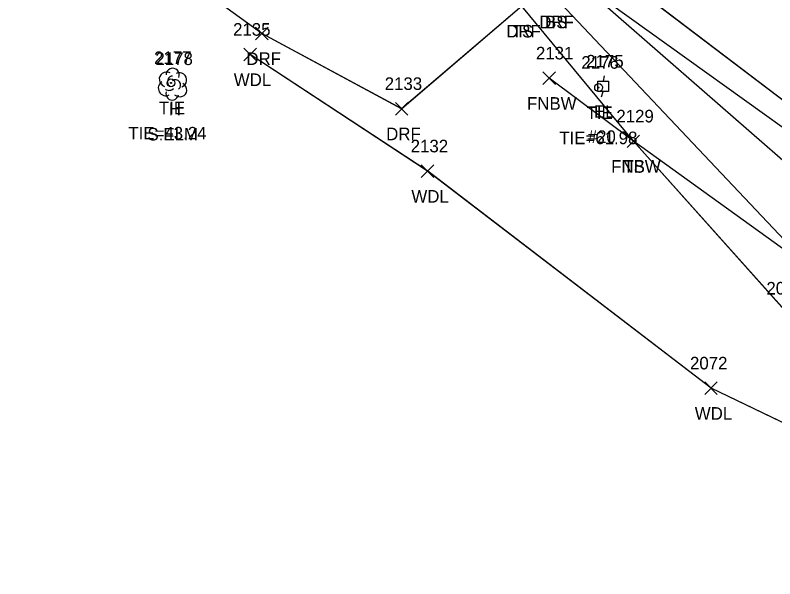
# Model space of a CAD drawing. Extents: x 1415642 to 1422021, y 544543 to 547232.
# Drawn here: x 1415652.6 to 1415773.3, y 547024.6 to 547114.3 of the extents above; entities that cross this region are included whole.
import ezdxf

# ---------------------------------------------------------------- set-up
doc = ezdxf.new("R2010")
doc.units = 0
for name, color, linetype in [('C_A', 7, 'Continuous'), ('C_C', 7, 'Continuous'), ('C_I', 7, 'Continuous'), ('CBP', 7, 'Continuous'), ('L_A', 7, 'Continuous'), ('L_C', 7, 'Continuous'), ('L_I', 7, 'Continuous'), ('L_TIC', 7, 'Continuous'), ('LAWA', 7, 'Continuous'), ('LELB', 7, 'Continuous'), ('LFNC', 7, 'Continuous'), ('LTD', 7, 'Continuous'), ('PET', 7, 'Continuous'), ('R_A', 7, 'Continuous'), ('R_I', 7, 'Continuous'), ('R_TIC', 7, 'Continuous'), ('RDF', 7, 'Continuous'), ('U_A', 7, 'Continuous'), ('U_C', 7, 'Continuous'), ('U_I', 7, 'Continuous'), ('UEPT', 7, 'Continuous')]:
    doc.layers.add(name, color=color, linetype=linetype)

msp = doc.modelspace()

# ---------------------------------------------------------------- linework, layer by layer
at = {"layer": 'CBP'}
for centre, radius in [((1415677.36, 547103.51), 0.625), ((1415677.36, 547103.51), 0.0833), ((1415745.31, 547102.76), 0.625), ((1415745.31, 547102.76), 0.0833)]:
    msp.add_circle(centre, radius, dxfattribs=at)
at = {"layer": 'L_TIC'}
for points in [[(1415688.93, 547107.01), (1415690.93, 547109.01)], [(1415690.93, 547107.01), (1415688.93, 547109.01)], [(1415736.47, 547103.24), (1415738.47, 547105.24)], [(1415738.47, 547103.24), (1415736.47, 547105.24)], [(1415749.83, 547093.22), (1415751.83, 547095.22)], [(1415751.83, 547093.22), (1415749.83, 547095.22)], [(1415749.83, 547093.22), (1415751.83, 547095.22)], [(1415751.83, 547093.22), (1415749.83, 547095.22)], [(1415717.14, 547088.46), (1415719.14, 547090.46)], [(1415719.14, 547088.46), (1415717.14, 547090.46)], [(1415762.17, 547053.94), (1415764.17, 547055.94)], [(1415764.17, 547053.94), (1415762.17, 547055.94)]]:
    msp.add_lwpolyline(points, dxfattribs=at)
at = {"layer": 'LAWA'}
for points in [[(1415914.11, 546834.35), (1415931.31, 546850.74), (1415944.85, 546869.92), (1415908.68, 546903.98), (1415882.09, 546945.44), (1415862.73, 546979.72), (1415851.29, 546999.16), (1415831.18, 547012.42), (1415802.21, 547036.19), (1415763.17, 547054.94), (1415718.14, 547089.46), (1415689.93, 547108.01)], [(1415914.12, 546834.35), (1415931.31, 546850.75), (1415944.86, 546869.92), (1415908.68, 546903.98), (1415882.1, 546945.44), (1415862.73, 546979.72), (1415851.29, 546999.15), (1415831.18, 547012.42), (1415802.2, 547036.19), (1415763.17, 547054.94), (1415718.15, 547089.45), (1415689.93, 547108.01)]]:
    msp.add_lwpolyline(points, dxfattribs=at)
at = {"layer": 'LELB'}
for points in [[(1415821.69, 547055.02), (1415783.27, 547083.61), (1415741.01, 547120.53), (1415723.94, 547132.39), (1415695.54, 547155.33), (1415675.42, 547170.57)], [(1415821.7, 547055.02), (1415783.28, 547083.61), (1415741.01, 547120.53), (1415723.94, 547132.38), (1415695.54, 547155.33), (1415675.42, 547170.56)], [(1415851.29, 546999.16), (1415835.48, 547016.01), (1415808.9, 547044.81), (1415779.47, 547073.63), (1415738.35, 547117.19), (1415722.7, 547128.21), (1415693.4, 547151.97), (1415674.17, 547168.64)], [(1415851.29, 546999.15), (1415835.48, 547016.02), (1415808.9, 547044.81), (1415779.47, 547073.63), (1415738.34, 547117.19), (1415722.7, 547128.21), (1415693.4, 547151.96), (1415674.17, 547168.64)], [(1415802.21, 547036.19), (1415775.31, 547066.85), (1415750.83, 547094.22), (1415733.1, 547115.73), (1415720.57, 547124.98), (1415690.99, 547148.71), (1415672.49, 547166.01)], [(1415802.2, 547036.19), (1415775.31, 547066.86), (1415750.83, 547094.23), (1415733.1, 547115.73), (1415720.57, 547124.98), (1415690.99, 547148.71), (1415672.49, 547166.01)], [(1415979.27, 546932.57), (1415964.6, 546940.59), (1415957.63, 546956.7), (1415934.73, 546972.98), (1415912.21, 546991.17), (1415886.95, 547011.09), (1415854.08, 547036.67), (1415824.18, 547059.44), (1415786.82, 547087.62), (1415741.01, 547120.53)], [(1415979.28, 546932.57), (1415964.61, 546940.59), (1415957.63, 546956.7), (1415934.74, 546972.98), (1415912.22, 546991.17), (1415886.96, 547011.09), (1415854.08, 547036.67), (1415824.19, 547059.44), (1415786.82, 547087.62), (1415741.01, 547120.53)]]:
    msp.add_lwpolyline(points, dxfattribs=at)
at = {"layer": 'LFNC'}
for points in [[(1415844.05, 547025.19), (1415815.91, 547049.29), (1415779.47, 547073.63), (1415750.83, 547094.22), (1415737.47, 547104.24)], [(1415844.05, 547025.19), (1415815.91, 547049.29), (1415779.47, 547073.63), (1415750.83, 547094.23), (1415737.47, 547104.24)]]:
    msp.add_lwpolyline(points, dxfattribs=at)
at = {"layer": 'LTD'}
msp.add_line((1415677.58, 547103.35), (1415677.58, 547103.35), dxfattribs=at)
msp.add_line((1415677.58, 547103.35), (1415677.58, 547103.35), dxfattribs=at)
msp.add_arc((1415677.63, 547104.79), 1.05, 335.5272, 180.9563, dxfattribs=at)
for centre, major_axis, ratio, start_param, end_param in [((1415676.79, 547104.02), (1.21, -0.51), 0.895232, 1.570796, 4.712389), ((1415677.38, 547103.81), (-0.208, -0.792), 0.645439, 3.141593, 6.283185), ((1415678.63, 547103.94), (-1.14, -0.48), 0.949671, 1.570796, 4.712389), ((1415676.5, 547102.64), (0.58, -1.04), 0.959034, 3.141593, 6.283185), ((1415678.08, 547103.19), (-0.5, 0.667), 0.989748, 3.141593, 6.283185), ((1415678.58, 547102.52), (-1.09, 0.79), 0.841452, 1.570796, 4.712389), ((1415677.58, 547101.85), (0.26, 1.06), 0.942809, 1.570796, 4.712389), ((1415677.13, 547102.6), (-0.625, -0.083), 0.423636, 0, 3.141593)]:
    msp.add_ellipse(centre, major_axis=major_axis, ratio=ratio, start_param=start_param, end_param=end_param, dxfattribs=at)
at = {"layer": 'PET'}
for points in [[(1415982.21, 546942.39), (1415954.4, 546964.56), (1415923.45, 546987.94), (1415890.93, 547013.5), (1415855.69, 547039.7), (1415826.51, 547062.15), (1415788.27, 547090.37), (1415749.29, 547120.02), (1415723.83, 547138.72), (1415697.43, 547158.88), (1415677.46, 547174.08)], [(1415982.21, 546942.39), (1415954.4, 546964.56), (1415923.45, 546987.94), (1415890.93, 547013.5), (1415855.69, 547039.7), (1415826.51, 547062.15), (1415788.27, 547090.37), (1415749.28, 547120.03), (1415723.83, 547138.72), (1415697.43, 547158.88), (1415677.46, 547174.08)]]:
    msp.add_lwpolyline(points, dxfattribs=at)
at = {"layer": 'R_TIC'}
for points in [[(1415690.81, 547110.36), (1415692.81, 547112.36)], [(1415692.81, 547110.36), (1415690.81, 547112.36)], [(1415713.02, 547098.39), (1415715.02, 547100.39)], [(1415715.02, 547098.39), (1415713.02, 547100.39)]]:
    msp.add_lwpolyline(points, dxfattribs=at)
at = {"layer": 'RDF'}
for points in [[(1415749.29, 547120.02), (1415741.01, 547120.53), (1415738.35, 547117.19), (1415733.1, 547115.73), (1415714.02, 547099.39), (1415691.81, 547111.36), (1415669.4, 547127.58), (1415652.61, 547136.68)], [(1415749.28, 547120.03), (1415741.01, 547120.53), (1415738.34, 547117.19), (1415733.1, 547115.73), (1415714.01, 547099.4), (1415691.81, 547111.36), (1415669.4, 547127.58), (1415652.61, 547136.68)]]:
    msp.add_lwpolyline(points, dxfattribs=at)
at = {"layer": 'UEPT'}
for p, q in [((1415746.2, 547104.62), (1415746.03, 547103.79)), ((1415745.2, 547102.12), (1415745.2, 547103.79)), ((1415745.2, 547103.79), (1415746.87, 547103.79)), ((1415746.87, 547103.79), (1415746.87, 547102.12)), ((1415746.87, 547102.12), (1415745.2, 547102.12)), ((1415745.78, 547101.29), (1415746.03, 547102.12)), ((1415746.03, 547102.96), (1415746.03, 547102.96))]:
    msp.add_line(p, q, dxfattribs=at)

# ---------------------------------------------------------------- texts
at = {"layer": 'C_A'}
for p in [(1415675.44, 547098.51), (1415743.39, 547097.76)]:
    msp.add_text('TIE', height=2, dxfattribs=at).set_placement(p)
at = {"layer": 'C_C'}
for s, p in [('TIE=43.24', (1415670.59, 547094.51)), ('TIE=61.98', (1415739.06, 547093.76))]:
    msp.add_text(s, height=2, dxfattribs=at).set_placement(p)
at = {"layer": 'C_I'}
for s, p in [('2177', (1415674.67, 547106.51)), ('2176', (1415742.56, 547105.76))]:
    msp.add_text(s, height=2, dxfattribs=at).set_placement(p)
at = {"layer": 'L_A'}
for s, p in [('BS', (1415736.79, 547112.19)), ('TS', (1415731.51, 547110.73)), ('WDL', (1415687.34, 547103.01)), ('FNBW', (1415733.94, 547099.24)), ('H', (1415677.02, 547098.35)), ('FNBW', (1415747.3, 547089.22)), ('TS', (1415749.24, 547089.22)), ('WDL', (1415715.56, 547084.46)), ('WDL', (1415760.59, 547049.94))]:
    msp.add_text(s, height=2, dxfattribs=at).set_placement(p)
at = {"layer": 'L_C'}
msp.add_text('S.ELM', height=2, dxfattribs=at).set_placement((1415673.62, 547094.35))
at = {"layer": 'L_I'}
for s, p in [('2135', (1415687.23, 547111.01)), ('2131', (1415735.35, 547107.24)), ('2178', (1415674.89, 547106.35)), ('2129', (1415748.13, 547097.22)), ('2129', (1415748.13, 547097.22)), ('2132', (1415715.45, 547092.46)), ('2073', (1415771.97, 547069.85)), ('2072', (1415759.83, 547057.94))]:
    msp.add_text(s, height=2, dxfattribs=at).set_placement(p)
at = {"layer": 'R_A'}
for p in [(1415735.88, 547112.19), (1415730.63, 547110.73), (1415689.35, 547106.36), (1415711.55, 547094.39)]:
    msp.add_text('DRF', height=2, dxfattribs=at).set_placement(p)
at = {"layer": 'R_I'}
msp.add_text('2133', height=2, dxfattribs=at).set_placement((1415711.32, 547102.39))
at = {"layer": 'U_A'}
msp.add_text('EL', height=2, dxfattribs=at).set_placement((1415744.57, 547097.96))
at = {"layer": 'U_C'}
msp.add_text('#20', height=2, dxfattribs=at).set_placement((1415743.58, 547093.96))
at = {"layer": 'U_I'}
msp.add_text('2175', height=2, dxfattribs=at).set_placement((1415743.34, 547105.96))

doc.saveas('drawing.dxf')
